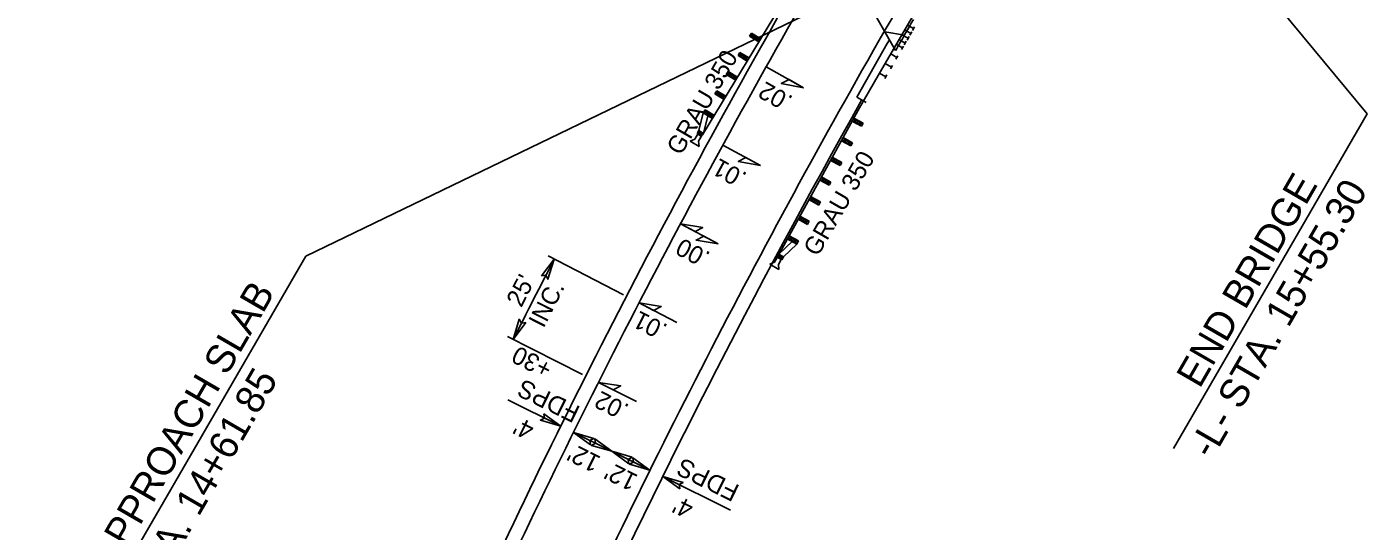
# Model space of a CAD drawing. Extents: x 1653308 to 1654073, y 597542 to 598622.
# Drawn here: x 1653497.3 to 1653874.2, y 597835.4 to 597977.2 of the extents above; entities that cross this region are included whole.
import ezdxf

# ---------------------------------------------------------------- set-up
doc = ezdxf.new("R2010")
doc.units = 0
for name, color, linetype in [('Default', 7, 'Continuous'), ('Prop Approach Slab', 7, 'Continuous'), ('Prop Approach Slab Hatching', 7, 'Continuous'), ('Prop Dimension', 7, 'Continuous'), ('Prop Dimension Text', 7, 'Continuous'), ('Prop EOT', 7, 'Continuous'), ('Prop Guardrail', 7, 'Continuous'), ('Prop Guardrail Anchor Unit CELL', 7, 'Continuous'), ('Prop Paved Shoulder', 7, 'Continuous'), ('Prop SBG', 7, 'Continuous'), ('Prop Structure Anchor Unit CELL', 7, 'Continuous'), ('Prop Superelevation  Arrow CELL', 7, 'Continuous'), ('Prop Superelevation Label', 7, 'Continuous'), ('Prop Terminator CELL', 7, 'Continuous')]:
    doc.layers.add(name, color=color, linetype=linetype)

msp = doc.modelspace()

# ---------------------------------------------------------------- linework, layer by layer
at = {"layer": 'Default'}
for p, q in [((1653739.84, 597973.54), (1653739.26, 597972.52)), ((1653733.27, 597955.9), (1653730.67, 597957.39))]:
    msp.add_line(p, q, dxfattribs=at)
at = {"layer": 'Prop Approach Slab'}
msp.add_line((1653741.61, 597970.59), (1653721.52, 598005.47), dxfattribs=at)
msp.add_arc((1655696.35, 596851.16), 2252.58, 149.9451, 150.2012, dxfattribs=at)
at = {"layer": 'Prop Approach Slab Hatching'}
msp.add_line((1653738.6, 597975.83), (1653744.06, 597974.86), dxfattribs=at)
at = {"layer": 'Prop Dimension'}
for p, q in [((1653778.21, 598068.66), (1653874.22, 597952.72)), ((1653731.56, 597988.04), (1653575.7, 597912.69)), ((1653874.22, 597952.72), (1653819.71, 597858.59)), ((1653505.04, 597790.67), (1653575.7, 597912.69)), ((1653643.91, 597912.78), (1653665.07, 597901.84)), ((1653632.44, 597890.07), (1653653.53, 597879.45)), ((1653632.51, 597872.3), (1653647.43, 597864.92)), ((1653651.01, 597863.14), (1653661.77, 597857.82)), ((1653672.52, 597852.5), (1653661.77, 597857.82)), ((1653695.2, 597841.28), (1653676.11, 597850.73))]:
    msp.add_line(p, q, dxfattribs=at)
msp.add_arc((1655696.35, 596851.16), 2308.84, 152.64981, 153.28082, dxfattribs=at)
at = {"layer": 'Prop EOT'}
for radius, end in [(2282, 155.30659), (2258, 155.29325)]:
    msp.add_arc((1655696.35, 596851.16), radius, 149.9451, end, dxfattribs=at)
at = {"layer": 'Prop Guardrail'}
msp.add_line((1653731.1, 597953.79), (1653737.11, 597964.18), dxfattribs=at)
at = {"layer": 'Prop Guardrail Anchor Unit CELL'}
for p, q in [((1653711.52, 597986.79), (1653687.3, 597946.81)), ((1653701.07, 597975.42), (1653700.55, 597974.56)), ((1653703.67, 597973.84), (1653701.07, 597975.42)), ((1653701.85, 597973.77), (1653701.07, 597975.42)), ((1653700.55, 597974.56), (1653702.37, 597974.63)), ((1653703.16, 597972.98), (1653700.55, 597974.56)), ((1653702.37, 597974.63), (1653701.85, 597973.77)), ((1653703.67, 597973.84), (1653701.85, 597973.77)), ((1653702.37, 597974.63), (1653703.16, 597972.98)), ((1653697.81, 597970.02), (1653697.29, 597969.17)), ((1653697.29, 597969.17), (1653699.11, 597969.24)), ((1653699.89, 597967.59), (1653697.29, 597969.17)), ((1653700.41, 597968.45), (1653697.81, 597970.02)), ((1653698.59, 597968.38), (1653697.81, 597970.02)), ((1653699.11, 597969.24), (1653698.59, 597968.38)), ((1653700.41, 597968.45), (1653698.59, 597968.38)), ((1653699.11, 597969.24), (1653699.89, 597967.59)), ((1653700.41, 597968.45), (1653699.89, 597967.59)), ((1653694.46, 597964.69), (1653693.94, 597963.83)), ((1653693.94, 597963.83), (1653695.8, 597963.87)), ((1653696.63, 597962.2), (1653693.94, 597963.83)), ((1653697.15, 597963.06), (1653694.46, 597964.69)), ((1653695.29, 597963.02), (1653694.46, 597964.69)), ((1653695.8, 597963.87), (1653695.29, 597963.02)), ((1653695.8, 597963.87), (1653696.63, 597962.2)), ((1653697.15, 597963.06), (1653695.29, 597963.02)), ((1653691.31, 597959.22), (1653690.8, 597958.37)), ((1653690.8, 597958.37), (1653692.6, 597958.45)), ((1653693.36, 597956.81), (1653690.8, 597958.37)), ((1653693.88, 597957.67), (1653691.31, 597959.22)), ((1653692.08, 597957.59), (1653691.31, 597959.22)), ((1653692.6, 597958.45), (1653692.08, 597957.59)), ((1653693.88, 597957.67), (1653692.08, 597957.59)), ((1653692.6, 597958.45), (1653693.36, 597956.81)), ((1653687.48, 597953.01), (1653686.28, 597948.01)), ((1653688, 597953.87), (1653687.48, 597953.01)), ((1653687.48, 597953.01), (1653689.31, 597953.07)), ((1653690.1, 597951.43), (1653687.48, 597953.01)), ((1653690.62, 597952.28), (1653688, 597953.87)), ((1653688.79, 597952.22), (1653688, 597953.87)), ((1653689.31, 597953.07), (1653688.79, 597952.22)), ((1653690.62, 597952.28), (1653688.79, 597952.22)), ((1653689.31, 597953.07), (1653690.1, 597951.43)), ((1653731.1, 597953.79), (1653708.53, 597912.85)), ((1653688.79, 597952.22), (1653687.56, 597947.23)), ((1653729.87, 597951.57), (1653729.39, 597950.69)), ((1653731.18, 597950.84), (1653729.39, 597950.69)), ((1653729.39, 597950.69), (1653732.01, 597949.24)), ((1653729.39, 597950.69), (1653730.7, 597949.97)), ((1653729.87, 597951.57), (1653732.5, 597950.12)), ((1653730.7, 597949.97), (1653729.87, 597951.57)), ((1653731.18, 597950.84), (1653730.7, 597949.97)), ((1653730.7, 597949.97), (1653732.5, 597950.12)), ((1653732.01, 597949.24), (1653731.18, 597950.84)), ((1653732.5, 597950.12), (1653732.01, 597949.24)), ((1653683.8, 597945.07), (1653685.13, 597945.66)), ((1653686.34, 597943.6), (1653683.8, 597945.07)), ((1653685.13, 597945.66), (1653686.16, 597947.43)), ((1653686.28, 597948.01), (1653685.76, 597947.15)), ((1653685.76, 597947.15), (1653687.56, 597947.23)), ((1653687.04, 597946.38), (1653685.76, 597947.15)), ((1653686.28, 597948.01), (1653686.02, 597947.58)), ((1653686.16, 597947.43), (1653686.69, 597947.12)), ((1653687.22, 597946.82), (1653686.19, 597945.05)), ((1653686.19, 597945.05), (1653686.34, 597943.6)), ((1653687.56, 597947.23), (1653686.28, 597948.01)), ((1653687.04, 597946.38), (1653686.28, 597948.01)), ((1653686.69, 597947.12), (1653687.22, 597946.82)), ((1653728.16, 597945.31), (1653726.35, 597945.17)), ((1653726.35, 597945.17), (1653729.02, 597943.7)), ((1653726.83, 597946.05), (1653729.5, 597944.57)), ((1653726.83, 597946.05), (1653727.68, 597944.43)), ((1653728.16, 597945.31), (1653727.68, 597944.43)), ((1653729.02, 597943.7), (1653728.16, 597945.31)), ((1653727.68, 597944.43), (1653729.5, 597944.57)), ((1653729.5, 597944.57), (1653729.02, 597943.7)), ((1653725.12, 597939.79), (1653723.3, 597939.65)), ((1653723.3, 597939.65), (1653725.97, 597938.18)), ((1653723.79, 597940.53), (1653726.46, 597939.06)), ((1653723.79, 597940.53), (1653724.64, 597938.92)), ((1653725.12, 597939.79), (1653724.64, 597938.92)), ((1653724.64, 597938.92), (1653726.46, 597939.06)), ((1653725.97, 597938.18), (1653725.12, 597939.79)), ((1653726.46, 597939.06), (1653725.97, 597938.18)), ((1653720.75, 597935.01), (1653720.26, 597934.13)), ((1653722.07, 597934.28), (1653720.26, 597934.13)), ((1653720.26, 597934.13), (1653722.92, 597932.67)), ((1653720.75, 597935.01), (1653723.4, 597933.55)), ((1653720.75, 597935.01), (1653721.59, 597933.4)), ((1653722.07, 597934.28), (1653721.59, 597933.4)), ((1653721.59, 597933.4), (1653723.4, 597933.55)), ((1653722.92, 597932.67), (1653722.07, 597934.28)), ((1653723.4, 597933.55), (1653722.92, 597932.67)), ((1653719.08, 597928.74), (1653717.22, 597928.62)), ((1653717.22, 597928.62), (1653719.97, 597927.1)), ((1653717.7, 597929.49), (1653720.45, 597927.98)), ((1653717.7, 597929.49), (1653718.59, 597927.86)), ((1653719.08, 597928.74), (1653718.59, 597927.86)), ((1653718.59, 597927.86), (1653720.45, 597927.98)), ((1653719.97, 597927.1), (1653719.08, 597928.74)), ((1653720.45, 597927.98), (1653719.97, 597927.1)), ((1653715.98, 597923.25), (1653714.18, 597923.1)), ((1653714.18, 597923.1), (1653716.81, 597921.65)), ((1653714.66, 597923.97), (1653717.29, 597922.53)), ((1653714.66, 597923.97), (1653715.49, 597922.37)), ((1653715.98, 597923.25), (1653715.49, 597922.37)), ((1653715.49, 597922.37), (1653717.29, 597922.53)), ((1653716.81, 597921.65), (1653715.98, 597923.25)), ((1653717.29, 597922.53), (1653716.81, 597921.65)), ((1653711.62, 597918.45), (1653714.3, 597916.98)), ((1653711.62, 597918.45), (1653712.48, 597916.84)), ((1653712.48, 597916.84), (1653708.77, 597913.29)), ((1653713.82, 597916.1), (1653710.09, 597912.56)), ((1653712.96, 597917.71), (1653711.14, 597917.58)), ((1653711.14, 597917.58), (1653713.82, 597916.1)), ((1653712.96, 597917.71), (1653712.48, 597916.84)), ((1653712.48, 597916.84), (1653714.3, 597916.98)), ((1653713.82, 597916.1), (1653712.96, 597917.71)), ((1653714.3, 597916.98), (1653713.82, 597916.1)), ((1653707.56, 597911.01), (1653706.23, 597910.42)), ((1653708.58, 597912.78), (1653707.56, 597911.01)), ((1653708.29, 597912.41), (1653710.09, 597912.56)), ((1653708.29, 597912.41), (1653709.6, 597911.69)), ((1653709.11, 597912.48), (1653708.58, 597912.78)), ((1653708.62, 597910.4), (1653709.64, 597912.18)), ((1653708.77, 597913.29), (1653710.09, 597912.56)), ((1653709.6, 597911.69), (1653708.77, 597913.29)), ((1653709.64, 597912.18), (1653709.11, 597912.48)), ((1653710.09, 597912.56), (1653709.6, 597911.69)), ((1653710.09, 597912.56), (1653709.85, 597912.12)), ((1653706.23, 597910.42), (1653708.78, 597908.95)), ((1653708.78, 597908.95), (1653708.62, 597910.4))]:
    msp.add_line(p, q, dxfattribs=at)
at = {"layer": 'Prop Paved Shoulder'}
for radius, start, end in [(2286, 149.71581, 155.30659), (2254, 150.63058, 155.29325)]:
    msp.add_arc((1655696.35, 596851.16), radius, start, end, dxfattribs=at)
at = {"layer": 'Prop SBG'}
msp.add_line((1653730.67, 597957.39), (1653739.26, 597972.52), dxfattribs=at)
at = {"layer": 'Prop Structure Anchor Unit CELL'}
for p, q in [((1653746.5, 597980.41), (1653737.11, 597964.18)), ((1653743.37, 597975), (1653745.1, 597974)), ((1653744.15, 597976.35), (1653745.88, 597975.35)), ((1653744.93, 597977.7), (1653746.66, 597976.7)), ((1653746.17, 597975.85), (1653745.59, 597974.85)), ((1653746.95, 597977.2), (1653746.38, 597976.21)), ((1653741.8, 597972.29), (1653743.53, 597971.29)), ((1653742.58, 597973.65), (1653744.32, 597972.64)), ((1653743.82, 597971.79), (1653743.25, 597970.8)), ((1653744.6, 597973.14), (1653744.03, 597972.15)), ((1653745.38, 597974.49), (1653744.81, 597973.5)), ((1653740.24, 597969.59), (1653741.97, 597968.59)), ((1653742.25, 597969.08), (1653741.68, 597968.09)), ((1653737.11, 597964.18), (1653738.84, 597963.18)), ((1653739.12, 597963.67), (1653738.55, 597962.68)), ((1653738.67, 597966.88), (1653740.4, 597965.88)), ((1653740.69, 597966.38), (1653740.12, 597965.39))]:
    msp.add_line(p, q, dxfattribs=at)
at = {"layer": 'Prop Superelevation  Arrow CELL'}
msp.add_line((1653658.02, 597877.19), (1653668.74, 597871.79), dxfattribs=at)
for points in [[(1653715.65, 597960.1), (1653709.44, 597961.28), (1653711.62, 597962.36)], [(1653703.56, 597938.22), (1653697.34, 597939.33), (1653699.5, 597940.43)], [(1653681.11, 597921.83), (1653687.35, 597920.78), (1653685.2, 597919.66)], [(1653691.71, 597916.2), (1653685.47, 597917.25), (1653687.63, 597918.37)], [(1653669.44, 597899.57), (1653675.69, 597898.59), (1653673.55, 597897.45)], [(1653658.02, 597877.19), (1653664.28, 597876.28), (1653662.15, 597875.11)]]:
    msp.add_lwpolyline(points, close=True, dxfattribs=at)
at = {"layer": 'Prop Superelevation Label'}
for p, q in [((1653715.65, 597960.1), (1653705.18, 597965.96)), ((1653703.56, 597938.22), (1653693.03, 597943.96)), ((1653681.11, 597921.83), (1653691.71, 597916.2)), ((1653680.1, 597894.06), (1653669.44, 597899.57))]:
    msp.add_line(p, q, dxfattribs=at)
at = {"layer": 'Prop Terminator CELL'}
for points in [[(1653642.03, 597907.17), (1653645.6, 597911.91), (1653643.83, 597906.21), (1653643.25, 597907.35)], [(1653637.58, 597894.02), (1653634.05, 597889.26), (1653635.76, 597894.97), (1653636.36, 597893.84)], [(1653642.63, 597868.41), (1653647.43, 597864.92), (1653641.7, 597866.59), (1653642.83, 597867.19)], [(1653655.8, 597859.65), (1653651.01, 597863.14), (1653656.74, 597861.47), (1653655.61, 597860.87)], [(1653656.97, 597861.32), (1653661.77, 597857.82), (1653656.04, 597859.5), (1653657.17, 597860.1)], [(1653666.56, 597854.33), (1653661.77, 597857.82), (1653667.5, 597856.15), (1653666.37, 597855.55)], [(1653667.73, 597855.99), (1653672.52, 597852.5), (1653666.79, 597854.17), (1653667.92, 597854.78)], [(1653680.9, 597847.23), (1653676.11, 597850.73), (1653681.84, 597849.05), (1653680.71, 597848.45)]]:
    msp.add_lwpolyline(points, close=True, dxfattribs=at)

# ---------------------------------------------------------------- texts
at = {"layer": 'Prop Dimension Text'}
for s, height, rotation, p in [('END BRIDGE', 8, 59.9255, (1653827.1, 597875.23)), ('-L- STA. 15+55.30', 8, 59.9255, (1653830.59, 597855.32)), ("25'", 5, 62.9653, (1653636.33, 597898.06)), ('BEGIN APPROACH SLAB', 8, 59.9255, (1653503.75, 597792.94)), ('INC.', 5, 62.9653, (1653642.59, 597892.24)), ('+30', 5, 153.2808, (1653645.5, 597882.53)), ('-L- STA. 14+61.85', 8, 59.9255, (1653524.13, 597802.18)), ('FDPS', 5.103, 153.675, (1653653.26, 597870.22)), ("4'", 5.103, 153.675, (1653640.41, 597865.36)), ("12'", 5.103, 153.675, (1653659.01, 597856.16)), ('FDPS', 5.103, 153.675, (1653698.05, 597848.06)), ("12'", 5.103, 153.675, (1653669.45, 597850.99)), ("4'", 5.103, 153.675, (1653685.21, 597843.2))]:
    msp.add_text(s, height=height, rotation=rotation, dxfattribs=at).set_placement(p)
at = {"layer": 'Prop Guardrail'}
msp.add_text('GRAU 350', height=5, rotation=59.9255, dxfattribs=at).set_placement((1653719.7, 597912.36))
at = {"layer": 'Prop Guardrail Anchor Unit CELL'}
msp.add_text('GRAU 350', height=5, rotation=59.9255, dxfattribs=at).set_placement((1653681.23, 597940.79))
at = {"layer": 'Prop Superelevation Label'}
for s, rotation, p in [('.02', 150.7568, (1653713.04, 597957.48)), ('.01', 151.3878, (1653700.12, 597935.93)), ('.00', 152.0188, (1653689.81, 597913.6)), ('.01', 153.2808, (1653677.83, 597893.28)), ('.02', 153.2808, (1653666.99, 597870.76))]:
    msp.add_text(s, height=5, rotation=rotation, dxfattribs=at).set_placement(p)

doc.saveas('drawing.dxf')
